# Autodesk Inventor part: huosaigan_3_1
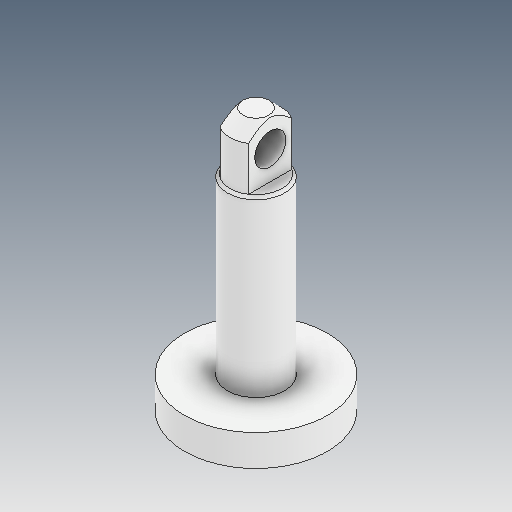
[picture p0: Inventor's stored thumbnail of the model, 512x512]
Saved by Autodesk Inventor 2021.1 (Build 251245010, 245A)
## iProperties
Created: 2021-05
Part Number: huosaigan_3_1
Material: Ogólny
Document SubType Name: Modeling
Designer: user
Density: 1 g/cm^3
Appearance: Domyślna
Author: user
Revision Number: ÈÎºÎ
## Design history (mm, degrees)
feature "ÊäÈë1"
node "Bryła1"
